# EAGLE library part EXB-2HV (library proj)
Panasonic 8 x 0402 resistor array
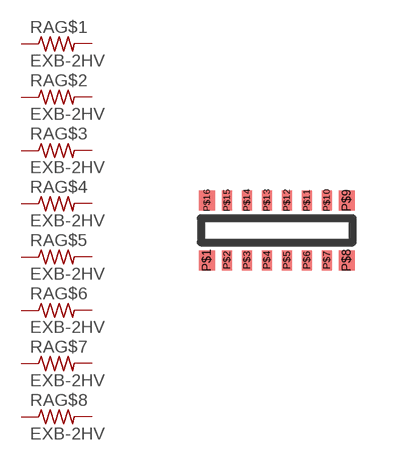
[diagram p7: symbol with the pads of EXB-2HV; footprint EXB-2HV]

Designator prefix RA; gates G$1=R-US-1 G$2=R-US-1 G$3=R-US-1 G$4=R-US-1 G$5=R-US-1 G$6=R-US-1 G$7=R-US-1 G$8=R-US-1

## EXB-2HV  [EXB-2HV]
P$1  G$1:1  pas
P$2  G$2:1  pas
P$3  G$3:1  pas
P$4  G$4:1  pas
P$5  G$5:1  pas
P$6  G$6:1  pas
P$7  G$7:1  pas
P$8  G$8:1  pas
P$9  G$8:2  pas
P$10  G$7:2  pas
P$11  G$6:2  pas
P$12  G$5:2  pas
P$13  G$4:2  pas
P$14  G$3:2  pas
P$15  G$2:2  pas
P$16  G$1:2  pas

## Footprint EXB-2HV (pad centres in mm)
Panasonic 0402 resistor network EXB-2HV
smd 0.4 x 0.5: P$1 -1.75,-0.75; P$8 1.75,-0.75; P$9 1.75,0.75; P$16 -1.75,0.75
smd 0.25 x 0.5: P$2 -1.25,-0.75; P$3 -0.75,-0.75; P$4 -0.25,-0.75; P$5 0.25,-0.75; P$6 0.75,-0.75; P$7 1.25,-0.75; P$10 1.25,0.75; P$11 0.75,0.75; P$12 0.25,0.75; P$13 -0.25,0.75; P$14 -0.75,0.75; P$15 -1.25,0.75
